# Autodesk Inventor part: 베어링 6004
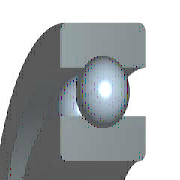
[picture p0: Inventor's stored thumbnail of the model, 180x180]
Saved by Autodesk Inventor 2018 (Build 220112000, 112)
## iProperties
IsCustomPart: 1
Created: 2012-02
Part Number: 베어링 6004
Material: 강철, 연강
Description: 깊은 그루브 볼 베어링
Document SubType Name: Modeling
Standard: KS B 2023
Designer: mduedu
Standards Organization: KS
Language: ko-KR
Size Designation: 6004 - 20 x 42 x 12
Categories: <MemberInstance><Categories><Category DisplayName="샤프트 부품" InternalName="7f7aeb1f-a693-4053-b835-cee3144e0d98" Mnemonic="SHFT"><Category DisplayName="베어링" Inter
Density: 1 g/cm^3
Appearance: 노란색
Author: mduedu
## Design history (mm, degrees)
sketch "스케치" dims "d0" = 5.72 (= -0.26 x WD + 0.26 x BD)
  geometry: L1 (3.14, 15.5)-(8.86, 15.5); L2 (6, 15.5)-(6, 12.64); L3 (6, 15.5)-(6, 18.36); L4 (3.875, 13.586)-(0, 13.586); L5 (0, 10)-(12, 10); L6 (3.875, 17.414)-(0, 17.414); L7 (0, 21)-(12, 21); L8 (12, 10)-(12, 13.586); L9 (8.125, 13.586)-(12, 13.586); L10 (8.125, 17.414)-(12, 17.414); L11 (12, 21)-(12, 17.414); L12 (-1.4, 0)-(8.4, 0) reference; L13 (0, -0.3)-(0, 5.3) reference
  constraints: 22 end point, 4 point on line, 2 collinear, 2 perpendicular, 2 symmetric about line, 1 midpoint, 1 parallel, 14 other
  dimensions: "d9" = 20 diameter of L5 L12 (= WD); "d11" = 42 diameter of L7 L12 (= BD); "d12" = 12 distance between parallel lines of L8 L13 (= KB); "d13" = 27.172 diameter of L9 L12 (= 0.326 x BD + 0.674 x WD)
revolve "본체" stored, may be unused: angle "d6" = 90 deg
revolve "볼" stored, may be unused: angle "d7" = 90 deg
pattern_circular "IDS_ARRAYBALL[SIMPL:T]" dims angle "d3" = 360 deg
body "Solid1"
fillet "모깎기1" dims "d1" = 0.6 (= KRS)
other parameters: "WD" = 20 [user parameter; used in 5 equation terms], "BD" = 42 [user parameter; used in 5 equation terms], "KB" = 12 [user parameter; used in 1 equation term], "KRS" = 0.6 [user parameter; used in 1 equation term], "d4" = 0, "d5" = 0, "d8" = 0, "d14" = 0, "d15" = 0, "BBA" = 0 [user parameter], "BC0" = 5000000 [user parameter], "BC" = 9360000 [user parameter], "BR" = 21 (= 0.5 x BD) [user parameter]
